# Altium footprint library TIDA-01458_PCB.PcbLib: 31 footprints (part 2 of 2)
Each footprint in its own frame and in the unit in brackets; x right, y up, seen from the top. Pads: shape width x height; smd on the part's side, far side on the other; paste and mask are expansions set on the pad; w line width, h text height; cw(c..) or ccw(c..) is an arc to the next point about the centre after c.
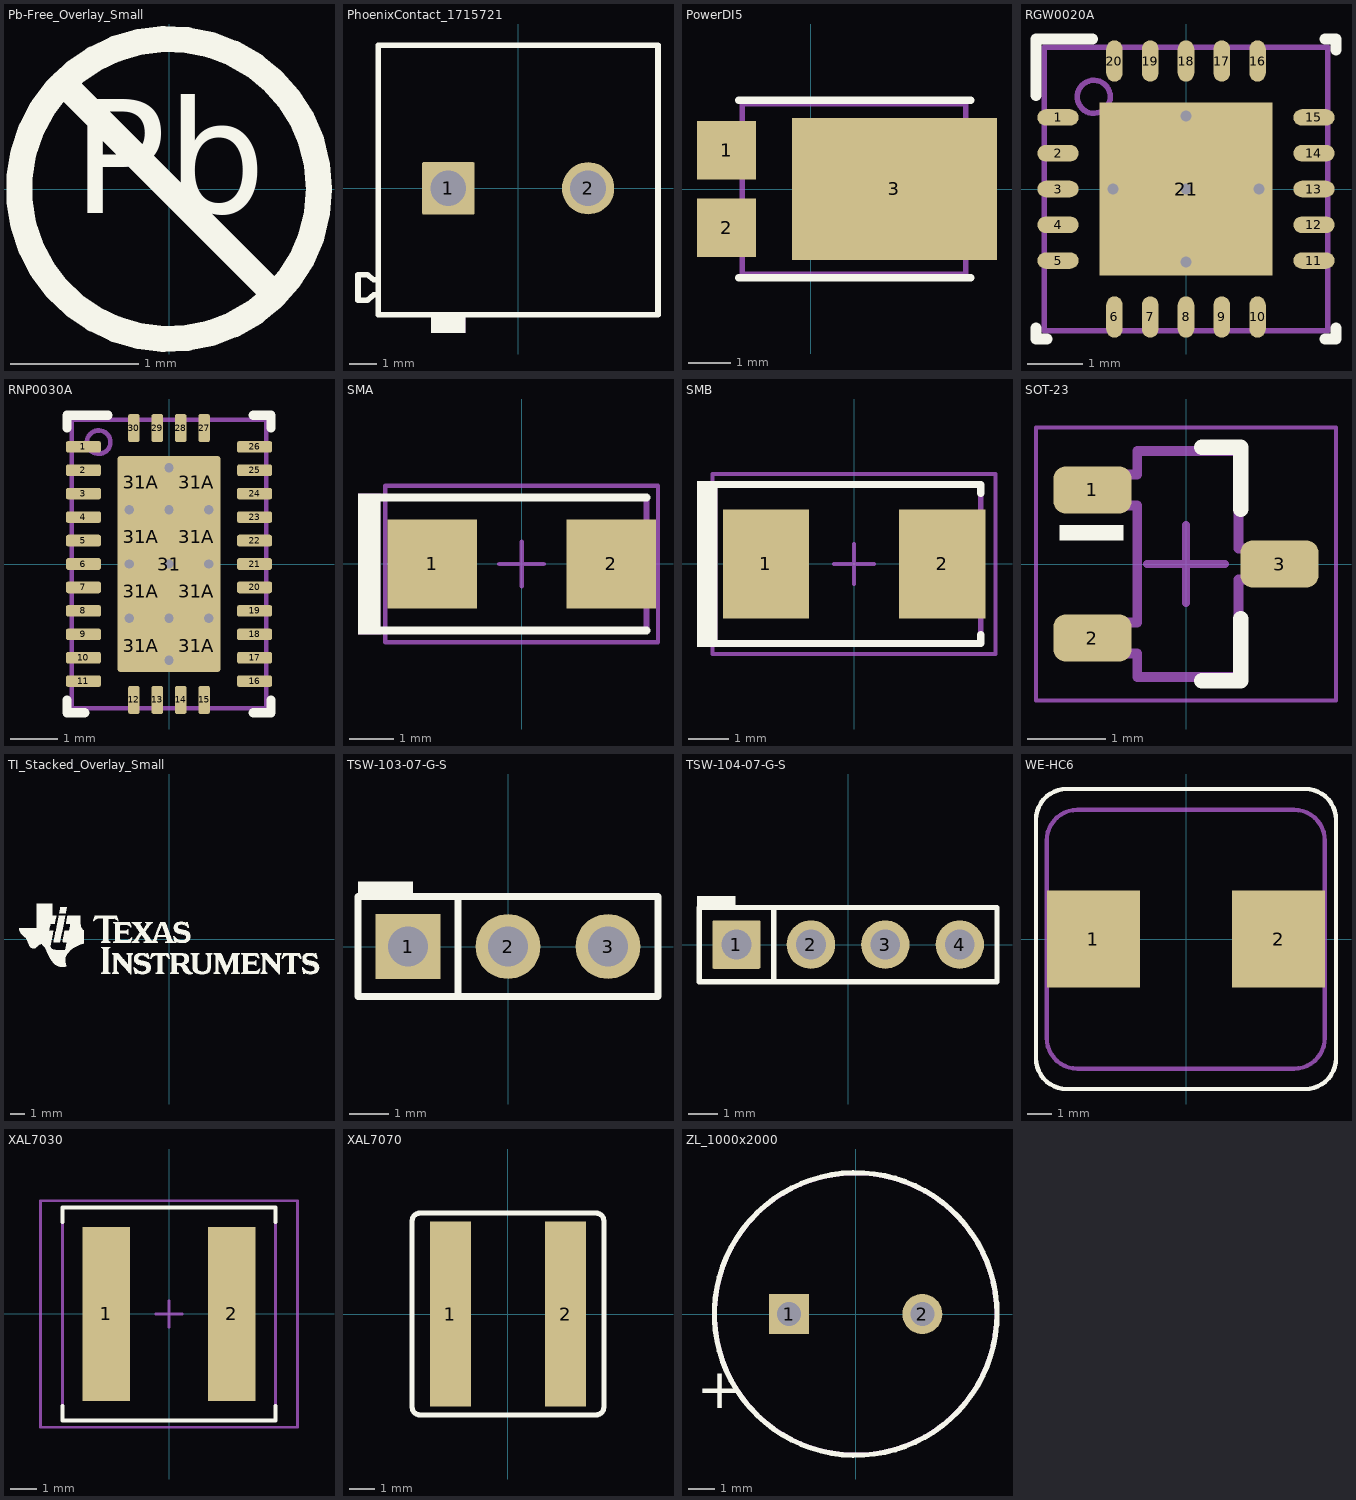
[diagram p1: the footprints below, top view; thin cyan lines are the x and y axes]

## Pb-Free_Overlay_Small [mm]
Top Overlay:
  circle w0.203: c0,0 r1.168
  lines w0.203: -0.826,0.826 0.826,-0.826
  text "Pb" at -0.752,-0.48 h1.52

## PhoenixContact_1715721 [mm] "Phoenix Contact 1715721 used on LM3445 design from Longmont"
height 13.8
pads (2):
  rrect5% 1.905x1.905 hole 1.3: 1(-2.54,0)
  round 1.9 hole 1.3: 2(2.54,0)
Top Overlay:
  rectangle: -3.17,-5.25 -1.92,-4.6
  lines w0.2: -5.08,-3.869 -5.247,-3.869 -5.479,-4.064 -5.821,-4.064 -5.821,-3.136 -5.479,-3.136 -5.247,-3.331 -5.08,-3.331 ; -5.08,-4.6 5.08,-4.6 5.08,5.2 -5.08,5.2 -5.08,-4.6
Mechanical 5:
  rectangle: -3.17,-5.25 -1.92,-4.6
  lines w0.1: -5.08,-3.869 -5.247,-3.869 -5.479,-4.064 -5.821,-4.064 -5.821,-3.136 -5.479,-3.136 -5.247,-3.331 -5.08,-3.331 ; -5.08,-4.6 -5.08,5.2 5.08,5.2 5.08,-4.6 -5.08,-4.6
  text ".Designator" at 0.762,-1.295 h1.52
3D body: height 14.2, standoff -3.5, extent -5.817,-4.598 5.084,5.202

## PowerDI5 [mm] "Diodes Inc recommended land pattern, ap02001.pdf rev 60"
height 1.15
pads (3):
  rect 1.4x1.39 smd: 1(-1.991,0.92) 2(-1.991,-0.92)
  rect 4.86x3.36 smd: 3(1.991,0)
Top Overlay:
  lines w0.18: -1.7,-2.1 3.8,-2.1 ; -1.7,2.1 3.8,2.1
Mechanical 5:
  lines w0.127: -1.619,-1.415 -2.269,-1.415 -2.269,-0.425 -1.619,-0.425 ; -1.619,-1.415 -1.619,-2.025 3.681,-2.025 3.681,-0.94 ; -1.619,-1.415 -1.619,-0.425 ; -1.619,-0.425 -1.619,0.425 ; -1.619,0.425 -2.269,0.425 -2.269,1.415 -1.619,1.415 ; -1.619,0.425 -1.619,1.415 ; -1.619,1.415 -1.619,2.025 3.681,2.025 3.681,0.94 ; 3.681,-0.94 4.331,-0.94 4.331,-0.5 4.181,-0.5 4.181,0.5 4.331,0.5 4.331,0.94 3.681,0.94 ; 3.681,-0.94 3.681,0.94
  text ".Designator" at 0.406,0.762 h1.02
3D body: height 1.17, standoff 0.02, extent -2.269,-2.025 4.331,2.025

## RGW0020A [mm] "QFN, 20-Leads, Body 5x5mm, Pitch 0.65mm, Thermal Pad 3.15x3.15mm, TI Recommended"
height 1
pads (21):
  oval 0.75x0.3 smd: 1(-2.325,1.3) 2(-2.325,0.65) 3(-2.325,0) 4(-2.325,-0.65) 5(-2.325,-1.3) 11(2.325,-1.3) 12(2.325,-0.65) 13(2.325,0) 14(2.325,0.65) 15(2.325,1.3)
  oval 0.3x0.75 smd: 6(-1.3,-2.325) 7(-0.65,-2.325) 8(0,-2.325) 9(0.65,-2.325) 10(1.3,-2.325) 16(1.3,2.325) 17(0.65,2.325) 18(0,2.325) 19(-0.65,2.325) 20(-1.3,2.325)
  rect 3.15x3.15 smd paste-1.575: 21(0,0)
via 0,1.325 diameter 0.5 hole 0.2
via -1.325,0 diameter 0.5 hole 0.2
via 0,0 diameter 0.5 hole 0.2
via 1.325,0 diameter 0.5 hole 0.2
via 0,-1.325 diameter 0.5 hole 0.2
Top Overlay:
  lines w0.2: -2.725,-2.525 -2.725,-2.725 -2.525,-2.725 ; -2.725,1.7 -2.725,2.725 -1.7,2.725 ; 2.525,-2.725 2.725,-2.725 2.725,-2.525 ; 2.525,2.725 2.725,2.725 2.725,2.525
Top Paste:
  rectangle: 0.1,0.1 1.468,1.468
  region: -0.1,1.468 -1.468,1.468 -1.468,0.1 -0.1,0.1
  region: -0.1,-0.1 -1.468,-0.1 -1.468,-1.468 -0.1,-1.468
  rectangle: 0.1,-1.468 1.468,-0.1
Mechanical 5:
  circle w0.1: c-1.675,1.675 r0.3
  lines w0.1: -2.575,-2.575 -2.575,2.575 2.575,2.575 2.575,-2.575 -2.575,-2.575
  text ".Designator" at 1.079,0.254 h1.02
3D body: height 1, standoff 0, extent -2.575,-2.575 2.575,2.575
3D body: height 1.01, standoff 0.5, extent -1.98,1.37 -1.37,1.98

## RNP0030A [mm] "QFN, 30-Leads, Body 6x4mm, Pitch 0.5mm, Thermal Pad 4.6x2.2mm"
height 0.8
pads (39):
  rrect40% 0.75x0.25 smd: 1(-1.825,2.5) 2(-1.825,2) 3(-1.825,1.5) 4(-1.825,1) 5(-1.825,0.5) 6(-1.825,0) 7(-1.825,-0.5) 8(-1.825,-1) 9(-1.825,-1.5) 10(-1.825,-2) 11(-1.825,-2.5) 16(1.825,-2.5) 17(1.825,-2) 18(1.825,-1.5) 19(1.825,-1) 20(1.825,-0.5) 21(1.825,0) 22(1.825,0.5) 23(1.825,1) 24(1.825,1.5) 25(1.825,2) 26(1.825,2.5)
  rrect40% 0.25x0.6 smd: 12(-0.75,-2.9) 13(-0.25,-2.9) 14(0.25,-2.9) 15(0.75,-2.9) 27(0.75,2.9) 28(0.25,2.9) 29(-0.25,2.9) 30(-0.75,2.9)
  rrect5% 2.2x4.6 smd paste-3: 31(0,0)
  rrect50% 0.98x0.96 on Top Paste: 31A(-0.59,-1.74) 31A(-0.59,-0.58) 31A(-0.59,0.58) 31A(-0.59,1.74) 31A(0.59,-1.74) 31A(0.59,-0.58) 31A(0.59,0.58) 31A(0.59,1.74)
via -0.85,0 diameter 0.5 hole 0.2
via 0,0 diameter 0.5 hole 0.2
via 0.85,0 diameter 0.5 hole 0.2
via 0,-2.05 diameter 0.5 hole 0.2
via 0.85,1.16 diameter 0.5 hole 0.2
via 0.85,-1.16 diameter 0.5 hole 0.2
via 0,2.05 diameter 0.5 hole 0.2
via 0,-1.16 diameter 0.5 hole 0.2
via 0,1.16 diameter 0.5 hole 0.2
via -0.85,-1.16 diameter 0.5 hole 0.2
via -0.85,1.16 diameter 0.5 hole 0.2
Top Overlay:
  lines w0.2: -2.175,-2.9 -2.175,-3.175 -1.8,-3.175 ; -2.175,2.9 -2.175,3.175 -1.3,3.175 ; 1.8,-3.175 2.175,-3.175 2.175,-2.9 ; 1.8,3.175 2.175,3.175 2.175,2.9
Mechanical 5:
  circle w0.1: c-1.5,2.6 r0.25
  lines w0.1: -2.075,-3.075 -2.075,3.075 2.075,3.075 2.075,-3.075 -2.075,-3.075
  text ".Designator" at 0.559,0.711 h1.02
3D body: height 0.8, standoff 0, extent -2.074,-3.074 2.074,3.074
3D body: height 0.81, standoff 0.8, extent -1.754,2.346 -1.246,2.854

## SMA [mm] "Molded Diode, 2-Leads, Body 4.3x2.6mm, IPC Medium Density, based on OnSemi component dimensions and land pattern"
height 2.27
pads (2):
  rect 2x2 smd: 1(-2,0) 2(2,0)
Top Overlay:
  rectangle: -3.658,-1.575 -3.15,1.575
  lines w0.178: -3.327,-1.486 2.794,-1.486 ; -3.327,1.486 2.794,1.486
Mechanical 5:
  rectangle: -3.658,-1.575 -3.15,1.575
  lines w0.127: -3.327,-1.486 2.794,-1.486 2.794,1.486 -3.327,1.486
  text ".Designator" at -1.397,-0.711 h1.02
Mechanical 15:
  lines w0.1: -0.5,0 0.5,0 ; 0,-0.5 0,0.5 ; -3.05,-1.75 3.05,-1.75 3.05,1.75 -3.05,1.75 -3.05,-1.75
3D body: height 2.42, standoff 0.02, extent -2.6,-1.3 2.6,1.3

## SMB [mm] "Molded Diode, 2-Leads, Body 5.4x3.6mm, IPC Medium Density, based on OnSemi component dimensions"
height 2.65
pads (2):
  rect 2.159x2.743 smd: 1(-2.21,0) 2(2.21,0)
Top Overlay:
  rectangle: -3.937,-2.083 -3.429,2.083
  lines w0.178: -3.607,-1.994 3.175,-1.994 3.175,-1.765 ; -3.607,1.994 3.175,1.994 3.175,1.765
Mechanical 5:
  rectangle: -3.937,-2.083 -3.429,2.083
  lines w0.127: -3.607,-1.994 3.175,-1.994 3.175,-1.765 3.175,1.765 3.175,1.994 -3.607,1.994
  text ".Designator" at 0.152,-0.965 h1.02
Mechanical 15:
  lines w0.1: -0.5,0 0.5,0 ; 0,-0.5 0,0.5 ; -3.55,-2.25 3.55,-2.25 3.55,2.25 -3.55,2.25 -3.55,-2.25
3D body: height 2.32, standoff 0.02, extent -2.7,-1.8 2.7,1.8

## SOT-23 [mm] "SOT23, 3-Leads, Body 2.9x1.3mm, Pitch 0.95mm, Lead Span 2.5mm, IPC Medium Density"
height 1.1
pads (3):
  rrect50% 1x0.6 smd: 1(-1.2,0.95) 2(-1.2,-0.95) 3(1.2,0)
Top Overlay:
  rectangle: -1.625,0.3 -0.8,0.5
  lines w0.2: 0.2,-1.5 0.7,-1.5 0.7,-0.7 ; 0.2,1.5 0.7,1.5 0.7,0.7
Mechanical 5:
  lines w0.127: -1.16,-1.15 -1.16,-0.75 -0.625,-0.75 -0.625,0.75 -1.16,0.75 -1.16,1.15 -0.625,1.15 -0.625,1.45 0.675,1.45 0.675,0.2 1.21,0.2 1.21,-0.2 0.675,-0.2 0.675,-1.45 -0.625,-1.45 -0.625,-1.15 -1.16,-1.15
  text ".Designator" at 0.261,-0.483 h0.64
Mechanical 15:
  lines w0.05: -1.925,-1.75 1.925,-1.75 1.925,1.75 -1.925,1.75 -1.925,-1.75
  lines w0.1: -0.5,0 0.5,0 ; 0,-0.5 0,0.5
3D body: height 1, standoff 0, extent -1.16,-1.45 1.21,1.45

## TI_Stacked_Overlay_Small [mm]
Top Overlay:
  drawing of 18 lines, arcs and shapes, not listed

## TSW-103-07-G-S [mm] "Samtec 100mil, 1x3, 230 mil above insulator"
height 8.382
pads (3):
  rect 1.65x1.65 hole 1.016: 1(-2.54,0)
  round 1.65 hole 1.016: 2(0,0) 3(2.54,0)
Top Overlay:
  rectangle: -3.81,1.27 -2.413,1.651
  lines w0.178: -1.27,-1.27 -1.27,1.27 ; -3.81,-1.27 3.81,-1.27 3.81,1.27 -3.81,1.27 -3.81,-1.27
Mechanical 5:
  rectangle: -3.048,-0.508 -2.032,0.508
  lines w0.127: -3.81,-1.27 -3.81,1.27 3.81,1.27 3.81,-1.27 -3.81,-1.27
  text ".Designator" at -0.711,0.864 h1.02
3D body: height 8.38, standoff -2.54, extent -3.81,-1.27 3.81,1.27

## TSW-104-07-G-S [mm] "Samtec 100mil, 1x4, 230 mil above insulator"
height 8.382
pads (4):
  rrect6% 1.65x1.65 hole 1.016: 1(-3.81,0)
  round 1.65 hole 1.016: 2(-1.27,0) 3(1.27,0) 4(3.81,0)
Top Overlay:
  rectangle: -5.156,1.27 -3.835,1.651
  lines w0.178: -2.54,-1.27 -2.54,1.27 ; -5.08,-1.27 -5.08,1.27 5.08,1.27 5.08,-1.27 -5.08,-1.27
Mechanical 5:
  lines w0.127: -5.08,-1.27 5.08,-1.27 5.08,1.27 -5.08,1.27 -5.08,-1.27
  text ".Designator" at 0.635,0.559 h1.02
3D body: height 8.38, standoff -2.54, extent -5.08,-1.27 5.08,1.27

## WE-HC6 [mm] "Wurth Electronik recommended land pattern"
height 5
pads (2):
  rect 3.85x4 smd: 1(-3.825,0) 2(3.825,0)
Top Overlay:
  lines w0.178: -6.2,-4.93 ccw(c-4.93,-4.93) -4.93,-6.2 0,-6.2 4.93,-6.2 ccw(c4.93,-4.93) 6.2,-4.93 6.2,0 6.2,4.93 ccw(c4.93,4.93) 4.93,6.2 0,6.2 -4.93,6.2 ccw(c-4.93,4.93) -6.2,4.93 -6.2,0 -6.2,-4.93
Mechanical 5:
  text ".Designator" at -1.825,-0.5 h1.02
Mechanical 13:
  lines w0.178: -5.76,-4.09 ccw(c-4.49,-4.09) -4.49,-5.36 4.47,-5.36 ccw(c4.47,-4.09) 5.74,-4.09 5.74,4.07 ccw(c4.47,4.07) 4.47,5.34 -4.49,5.34 ccw(c-4.49,4.07) -5.76,4.07 -5.76,-4.09
3D body: height 5, standoff 0, extent -5.77,-5.37 5.75,5.35

## XAL7030 [mm] "Coilcraft XAL7030 7.5 x.7.5 x 3.1 mm"
height 3.1
pads (2):
  rect 1.78x6.55 smd: 1(-2.36,0) 2(2.36,0)
Top Overlay:
  lines w0.152: -4,-3.46 -4,-4 4,-4 4,-3.46 ; -4,3.46 -4,4 4,4 4,3.46
Mechanical 5:
  lines w0.1: -4,-4 4,-4 4,4 -4,4 -4,-4
  text ".Designator" at -1.905,-0.508 h1.02
Mechanical 15:
  lines w0.1: -0.5,0 0.5,0 ; 0,-0.5 0,0.5 ; -4.825,-4.25 4.825,-4.25 4.825,4.25 -4.825,4.25 -4.825,-4.25
3D body: height 3.1, standoff 0, extent -4,-4 4,4

## XAL7070 [mm] "COILCRAFT"
height 7
pads (2):
  rect 1.63x7.33 smd: 1(-2.285,0) 2(2.285,0)
Top Overlay:
  lines w0.2: -3.8,-3.7 ccw(c-3.5,-3.7) -3.5,-4 3.5,-4 ccw(c3.5,-3.7) 3.8,-3.7 3.8,3.7 ccw(c3.5,3.7) 3.5,4 -3.5,4 ccw(c-3.5,3.7) -3.8,3.7 -3.8,-3.7
Mechanical 5:
  lines w0.1: -3.8,-3.7 ccw(c-3.5,-3.7) -3.5,-4 3.5,-4 ccw(c3.5,-3.7) 3.8,-3.7 3.8,3.7 ccw(c3.5,3.7) 3.5,4 -3.5,4 ccw(c-3.5,3.7) -3.8,3.7 -3.8,-3.7
  text ".Designator" at -1.118,-0.457 h1.02
3D body: height 7, standoff 0, extent -3.806,-4.006 3.806,4.006

## ZL_1000x2000 [mm] "Capacitor, Electrolytic, Radial; Body 10 x 20 mm (Dia.xH typ); Pin Spacing 5 mm (typ)"
height 22
pads (2):
  rect 1.5x1.5 hole 0.9: 1(-2.5,0)
  round 1.5 hole 0.9: 2(2.5,0)
Top Overlay:
  circle w0.2: c0,0 r5.3
  text "+" at -5.954,-3.531 h1.5
Mechanical 5:
  circle w0.1: c0,0 r5.25
  text ".Designator" at 0.345,-0.813 h1.02
  text "+" at -6.8,-0.7 h1.5
3D body: height 22.01, standoff -4, extent -5.209,-5.241 5.24,5.242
